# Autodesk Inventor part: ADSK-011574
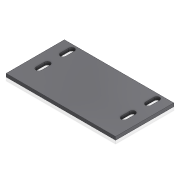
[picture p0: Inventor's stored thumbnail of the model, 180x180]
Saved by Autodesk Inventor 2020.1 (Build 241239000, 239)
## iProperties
Created: 2000-02
Part Number: ADSK-011574
Document SubType Name: Modeling
Designer: sspink
Material: Acier doux
Density: 7.86 g/cm^3
Appearance: Metal-Steel(Polish)
Mass: 987.016 g
Surface Area: 471.362 cm^2
Volume: 125.575 cm^3
Control State: 0
Master: False
Checked Out: False
Shininess: 60.0
Length Units: 11269
Angle Units: 11279
Time Units: 11290
Mass Units: 11283
Length Display Precision: 3
Angle Display Precision: 2
Compacted: True
Cutlength: 4.25
Material Description: FLAT,HRS,0.250X08.000
Material_Number: A084342
Dimensions: 6x108x203 mm
Mass: 0,987 kg
VLT_Material: Acier doux
Density: 7.859999999999999
Volumn: 196.64476800000017
Area: 470.96680000000003
PropertySet Name: Model Information
Author: sspink
Revision Number: -
Title: ADSK-011574
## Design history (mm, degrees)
node "Extrusion1" dims "d2" = 108, "d3" = 0
  sketch "Sketch1"
    geometry: L1 (0, 0)-(203, 0); L2 (203, 0)-(203, 6); L3 (203, 6)-(0, 6); L4 (0, 6)-(0, 0)
    constraints: 8 end point, 2 parallel, 1 horizontal, 1 perpendicular
    dimensions: "d0" = 203 distance of L1.start L1.end; "d1" = 6 distance between parallel lines of L1 L3
node "Extrusion2" dims "d20" = 25.4, "d21" = 0
  sketch "Sketch3"
    geometry: L1 (0, 0)-(93.496, 0); L2 (17.341, -25)-(27.659, -25); L3 (27.659, -25)-(27.659, -9); L4 (27.659, -9)-(17.341, -9); L5 (17.341, -9)-(17.341, -25); L6 (17.341, -70)-(27.659, -70); L7 (27.659, -70)-(27.659, -54); L8 (27.659, -54)-(17.341, -54); L9 (17.341, -54)-(17.341, -70); L10 (175.341, -70)-(185.659, -70); L11 (185.659, -70)-(185.659, -54); L12 (185.659, -54)-(175.341, -54); L13 (175.341, -54)-(175.341, -70); L14 (175.341, -25)-(185.659, -25); L15 (185.659, -25)-(185.659, -9); L16 (185.659, -9)-(175.341, -9); L17 (175.341, -9)-(175.341, -25); L18 (22.5, -70)-(22.5, -54); L19 (22.5, -25)-(22.5, -9); L20 (180.5, -70)-(180.5, -54); L21 (180.5, -25)-(180.5, -9); L22 (180.5, -62)-(22.5, -62); L23 (22.5, -62)-(22.5, -17); L24 (22.5, -17)-(180.5, -17); L25 (180.5, -17)-(180.5, -62); L26 (0, -108)-(203, -108) reference; L27 (203, 0)-(0, 0) reference; A1 r 5.159 centre (22.5, -9) between (27.659, -9) and (17.341, -9); A2 r 5.159 centre (22.5, -25) between (17.341, -25) and (27.659, -25); A3 r 5.159 centre (22.5, -54) between (27.659, -54) and (17.341, -54); A4 r 5.159 centre (22.5, -70) between (17.341, -70) and (27.659, -70); A5 r 5.159 centre (180.5, -9) between (185.659, -9) and (175.341, -9); A6 r 5.159 centre (180.5, -25) between (175.341, -25) and (185.659, -25); A7 r 5.159 centre (180.5, -54) between (185.659, -54) and (175.341, -54); A8 r 5.159 centre (180.5, -70) between (175.341, -70) and (185.659, -70); 5 further points
    constraints: 50 end point, 16 point on circle, 10 parallel, 8 centre point, 8 midpoint, 8 tangent, 6 horizontal, 5 perpendicular, 3 equal length, 3 equal radius, 3 vertical, 3 vertical alignment, 2 horizontal alignment
    dimensions: "d14" = 16 distance of L2.end L3.end; "d15" = 5.15938 radius of A2; "d22" = 45 distance of L24.end L22.start; "d23" = 158 distance of L22.start L22.end; "d26" = 17 distance between parallel lines of L27 L24
node "Solide1"
node "Corps solides"
node "Corps surfaciques"
